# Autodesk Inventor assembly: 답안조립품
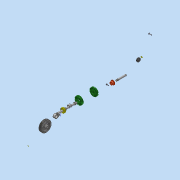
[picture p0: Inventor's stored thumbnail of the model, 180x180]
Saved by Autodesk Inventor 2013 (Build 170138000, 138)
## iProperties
Created: 2017-07
Part Number: 답안조립품
Document SubType Name: Assembly
Designer: Administrator
Author: Administrator
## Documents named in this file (16)
- C:\Users\Administrator\Desktop\470707V1006\답안조립품.iam
- C:\Users\Administrator\Desktop\470707V1006\볼트 M4 x 12.ipt
- C:\Users\Administrator\Desktop\470707V1006\부시.ipt
- C:\Users\Administrator\Desktop\470707V1006\슬라이드.ipt
- C:\Users\Administrator\Desktop\470707V1006\앞커버.ipt
- C:\Users\Administrator\Desktop\470707V1006\오일실 12 25 7.ipt
- C:\Users\Administrator\Desktop\470707V1006\키 4 x 4 x 10.ipt
- C:\Users\Administrator\Desktop\470707V1006\편심축.ipt
- C:\Users\Administrator\Desktop\470707V1006\핀 5 x 18.ipt
- C:\Users\Administrator\Desktop\470707V1006\고정핀 1.2 x  8.ipt
- C:\Users\Administrator\Desktop\470707V1006\뒤커버.ipt
- C:\Users\Administrator\Desktop\470707V1006\V벨트풀리.ipt
- C:\Users\Administrator\Desktop\470707V1006\링크.ipt
- C:\Users\Administrator\Desktop\470707V1006\멈춤나사 M3x8.ipt
- C:\Users\Administrator\Desktop\470707V1006\베어링 12 x 32 x 10.ipt
- C:\Users\Administrator\Desktop\470707V1006\본체.ipt
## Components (3 placed, 3 different names)
1. 고정핀 1.2 x  8:2
2. V벨트풀리:2
3. 핀 5 x 18:2
